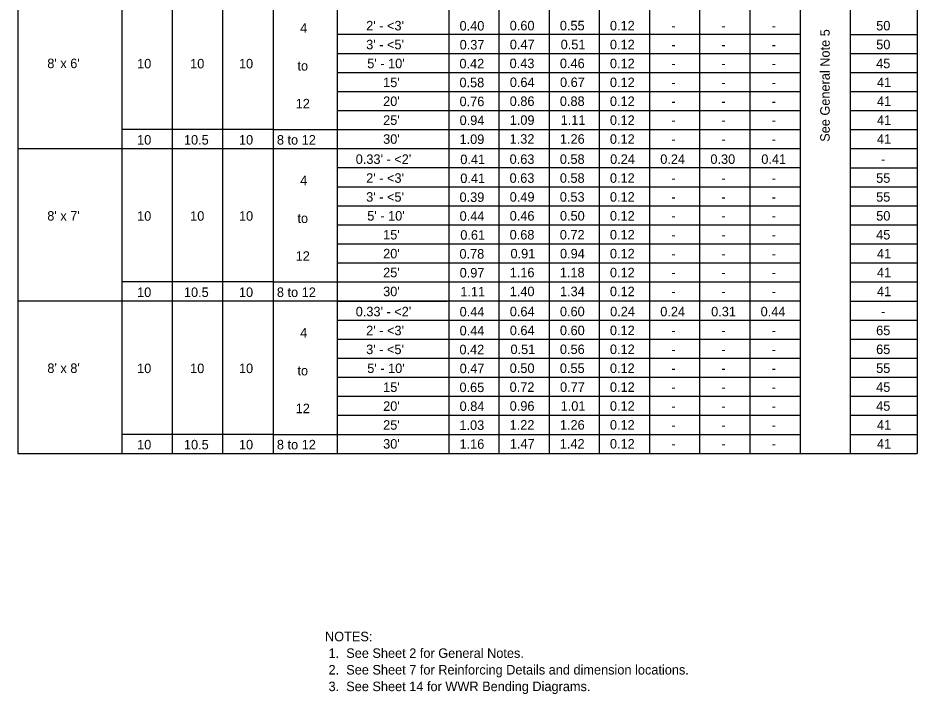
# Model space of a CAD drawing. Extents: x 10342.77 to 10344.98, y 76371.53 to 76372.62.
# Drawn here: x 10343.418 to 10344.012, y 76371.801 to 76372.249 of the extents above; entities that cross this region are included whole.
import ezdxf

# ---------------------------------------------------------------- set-up
doc = ezdxf.new("R2010")
doc.units = 0
doc.layers.add('AdhocPoint_dp', color=7, linetype='Continuous')
doc.layers.add('PlotBorder_dp', color=7, linetype='Continuous')

msp = doc.modelspace()

# ---------------------------------------------------------------- linework, layer by layer
at = {"layer": 'PlotBorder_dp'}
for p, q in [((10343.41763, 76372.53475), (10343.41763, 76371.96053)), ((10344.01237, 76372.53475), (10344.01237, 76371.96053)), ((10343.48627, 76372.51488), (10343.48627, 76371.96053)), ((10343.62871, 76372.51488), (10343.62871, 76371.96053)), ((10343.70259, 76372.51488), (10343.70259, 76371.96053)), ((10343.96818, 76372.51488), (10343.96818, 76371.96053)), ((10343.51963, 76372.50228), (10343.51963, 76371.96053)), ((10343.55299, 76372.50228), (10343.55299, 76371.96053)), ((10343.58635, 76372.50228), (10343.58635, 76371.96053)), ((10343.73579, 76372.47713), (10343.73579, 76371.96053)), ((10343.76899, 76372.47713), (10343.76899, 76371.96053)), ((10343.80219, 76372.47713), (10343.80219, 76371.96053)), ((10343.83539, 76372.47713), (10343.83539, 76371.96053)), ((10343.86858, 76372.47713), (10343.86858, 76371.96053)), ((10343.86858, 76372.47713), (10343.86858, 76371.96053)), ((10343.90178, 76372.47713), (10343.90178, 76371.96053)), ((10343.93498, 76372.47713), (10343.93498, 76371.96053)), ((10343.62871, 76372.23773), (10343.93498, 76372.23773)), ((10343.96818, 76372.23771), (10344.01237, 76372.23771)), ((10343.62871, 76372.22513), (10343.93498, 76372.22513)), ((10343.96818, 76372.22511), (10344.01237, 76372.22511)), ((10343.62871, 76372.21253), (10343.93498, 76372.21253)), ((10343.96818, 76372.21251), (10344.01237, 76372.21251)), ((10343.62871, 76372.19993), (10343.93498, 76372.19993)), ((10343.96818, 76372.19991), (10344.01237, 76372.19991)), ((10343.62871, 76372.18733), (10343.93498, 76372.18733)), ((10343.96818, 76372.18731), (10344.01237, 76372.18731)), ((10343.58635, 76372.17473), (10343.48627, 76372.17473)), ((10343.58635, 76372.17473), (10343.93498, 76372.17473)), ((10343.96818, 76372.17471), (10344.01237, 76372.17471)), ((10343.41763, 76372.16213), (10343.93498, 76372.16213)), ((10343.62931, 76372.16211), (10343.70148, 76372.16211)), ((10343.96818, 76372.16211), (10344.01237, 76372.16211)), ((10343.62871, 76372.14953), (10343.93498, 76372.14953)), ((10343.96818, 76372.14951), (10344.01237, 76372.14951)), ((10343.62871, 76372.13693), (10343.93498, 76372.13693)), ((10343.96818, 76372.13691), (10344.01237, 76372.13691)), ((10343.62871, 76372.12433), (10343.93498, 76372.12433)), ((10343.96818, 76372.12431), (10344.01237, 76372.12431)), ((10343.62871, 76372.11173), (10343.93498, 76372.11173)), ((10343.96818, 76372.11171), (10344.01237, 76372.11171)), ((10343.62871, 76372.09913), (10343.93498, 76372.09913)), ((10343.96818, 76372.09911), (10344.01237, 76372.09911)), ((10343.62871, 76372.08653), (10343.93498, 76372.08653)), ((10343.96818, 76372.08651), (10344.01237, 76372.08651)), ((10343.58635, 76372.07393), (10343.48627, 76372.07393)), ((10343.58635, 76372.07393), (10343.93498, 76372.07393)), ((10343.96818, 76372.07391), (10344.01237, 76372.07391)), ((10343.41763, 76372.06133), (10343.93498, 76372.06133)), ((10343.62931, 76372.06131), (10343.70148, 76372.06131)), ((10343.96818, 76372.06131), (10344.01237, 76372.06131)), ((10343.62871, 76372.04873), (10343.93498, 76372.04873)), ((10343.96818, 76372.04871), (10344.01237, 76372.04871)), ((10343.62871, 76372.03613), (10343.93498, 76372.03613)), ((10343.96818, 76372.03611), (10344.01237, 76372.03611)), ((10343.62871, 76372.02353), (10343.93498, 76372.02353)), ((10343.96818, 76372.02351), (10344.01237, 76372.02351)), ((10343.62871, 76372.01093), (10343.93498, 76372.01093)), ((10343.96818, 76372.01091), (10344.01237, 76372.01091)), ((10343.62871, 76371.99833), (10343.93498, 76371.99833)), ((10343.96818, 76371.99831), (10344.01237, 76371.99831)), ((10343.62871, 76371.98573), (10343.93498, 76371.98573)), ((10343.96818, 76371.98571), (10344.01237, 76371.98571)), ((10343.58635, 76371.97313), (10343.48627, 76371.97313)), ((10343.58635, 76371.97311), (10343.70148, 76371.97311)), ((10343.62871, 76371.97313), (10343.93498, 76371.97313)), ((10343.96818, 76371.97311), (10344.01237, 76371.97311)), ((10343.41763, 76371.96053), (10344.01237, 76371.96053))]:
    msp.add_line(p, q, dxfattribs=at)

# ---------------------------------------------------------------- texts
at = {"layer": 'AdhocPoint_dp'}
msp.add_text('See General Note 5', height=0.0063, rotation=90, dxfattribs=at).set_placement((10343.95463, 76372.16663))
for s, p in [('10', (10343.49644, 76372.21519)), ('10', (10343.53153, 76372.21519)), ('10', (10343.56382, 76372.21519)), ('10', (10343.49643, 76372.16478)), ('10.5', (10343.52742, 76372.16478)), ('10', (10343.56381, 76372.16478)), ('8 to 12', (10343.58891, 76372.16478)), ('10', (10343.49644, 76372.11441)), ('10', (10343.53153, 76372.11441)), ('10', (10343.56382, 76372.11441)), ('10', (10343.49643, 76372.06398)), ('10.5', (10343.52742, 76372.06398)), ('10', (10343.56381, 76372.06398)), ('8 to 12', (10343.58891, 76372.06398)), ('10', (10343.49644, 76372.01363)), ('10', (10343.53153, 76372.01363)), ('10', (10343.56382, 76372.01363)), ('10', (10343.49643, 76371.96318)), ('10.5', (10343.52742, 76371.96318)), ('10', (10343.56381, 76371.96318)), ('8 to 12', (10343.58891, 76371.96318))]:
    msp.add_text(s, height=0.0063, dxfattribs=at).set_placement(p)
at = {"layer": 'PlotBorder_dp'}
for s, p in [('4', (10343.60429, 76372.23873)), ("2' - <3'", (10343.64797, 76372.2403)), ('0.40', (10343.70975, 76372.24019)), ('0.60', (10343.74294, 76372.24035)), ('0.55', (10343.77609, 76372.24035)), ('0.12', (10343.80922, 76372.2403)), ('50', (10343.98538, 76372.2403)), ('-', (10343.84981, 76372.2403)), ('-', (10343.88302, 76372.2403)), ('-', (10343.9162, 76372.2403)), ("3' - <5'", (10343.64797, 76372.2278)), ('0.37', (10343.70981, 76372.22769)), ('0.47', (10343.74301, 76372.22785)), ('0.51', (10343.77663, 76372.22785)), ('0.12', (10343.80922, 76372.2278)), ('50', (10343.98538, 76372.2278)), ('-', (10343.84981, 76372.2278)), ('-', (10343.88302, 76372.2278)), ('-', (10343.9162, 76372.2278)), ("8' x 6'", (10343.43702, 76372.21535)), ("5' - 10'", (10343.64868, 76372.2153)), ('0.42', (10343.70967, 76372.21519)), ('0.43', (10343.74286, 76372.21535)), ('0.46', (10343.77613, 76372.21535)), ('0.12', (10343.80922, 76372.2153)), ('45', (10343.98533, 76372.2153)), ('to', (10343.60251, 76372.21373)), ('-', (10343.84981, 76372.2153)), ('-', (10343.88302, 76372.2153)), ('-', (10343.9162, 76372.2153)), ("15'", (10343.6592, 76372.2028)), ('0.58', (10343.70969, 76372.20269)), ('0.64', (10343.74299, 76372.20285)), ('0.67', (10343.77621, 76372.20285)), ('0.12', (10343.80922, 76372.2028)), ('41', (10343.98587, 76372.2028)), ('-', (10343.84981, 76372.2028)), ('-', (10343.88302, 76372.2028)), ('-', (10343.9162, 76372.2028)), ('12', (10343.60134, 76372.18873)), ("20'", (10343.6592, 76372.1903)), ('0.76', (10343.70973, 76372.19019)), ('0.86', (10343.74293, 76372.19035)), ('0.88', (10343.77609, 76372.19035)), ('0.12', (10343.80922, 76372.1903)), ('-', (10343.84981, 76372.1903)), ('-', (10343.88302, 76372.1903)), ('-', (10343.9162, 76372.1903)), ('41', (10343.98587, 76372.1903)), ("25'", (10343.6592, 76372.1778)), ('0.94', (10343.70979, 76372.17769)), ('1.09', (10343.74293, 76372.17785)), ('1.11', (10343.77663, 76372.17785)), ('0.12', (10343.80922, 76372.1778)), ('-', (10343.84981, 76372.1778)), ('-', (10343.88302, 76372.1778)), ('-', (10343.9162, 76372.1778)), ('41', (10343.98587, 76372.1778)), ("30'", (10343.6592, 76372.1653)), ('1.09', (10343.70973, 76372.16519)), ('1.32', (10343.74287, 76372.16535)), ('1.26', (10343.77613, 76372.16535)), ('0.12', (10343.80922, 76372.1653)), ('-', (10343.84981, 76372.1653)), ('-', (10343.88302, 76372.1653)), ('-', (10343.9162, 76372.1653)), ('41', (10343.98587, 76372.1653)), ("0.33' - <2'", (10343.64107, 76372.15201)), ('0.41', (10343.71024, 76372.15186)), ('0.63', (10343.74286, 76372.15201)), ('0.58', (10343.77609, 76372.15201)), ('0.24', (10343.80935, 76372.15201)), ('0.24', (10343.84253, 76372.15201)), ('0.30', (10343.87569, 76372.15201)), ('0.41', (10343.90936, 76372.15201)), ('-', (10343.98864, 76372.15201)), ('4', (10343.60429, 76372.13793)), ("2' - <3'", (10343.64797, 76372.13951)), ('0.41', (10343.71024, 76372.13936)), ('0.63', (10343.74286, 76372.13951)), ('0.58', (10343.77609, 76372.13951)), ('0.12', (10343.80922, 76372.13951)), ('55', (10343.98533, 76372.13951)), ('-', (10343.84981, 76372.13951)), ('-', (10343.88302, 76372.13951)), ('- ', (10343.9162, 76372.13951)), ("3' - <5'", (10343.64797, 76372.12701)), ('0.39', (10343.70973, 76372.12686)), ('0.49', (10343.74293, 76372.12701)), ('0.53', (10343.77606, 76372.12701)), ('0.12', (10343.80922, 76372.12701)), ('55', (10343.98533, 76372.12701)), ('-', (10343.84981, 76372.12701)), ('-', (10343.88302, 76372.12701)), ('-', (10343.9162, 76372.12701)), ("8' x 7'", (10343.43702, 76372.11451)), ("5' - 10'", (10343.64868, 76372.11451)), ('0.44', (10343.70979, 76372.11436)), ('0.46', (10343.74293, 76372.11451)), ('0.50', (10343.77615, 76372.11451)), ('0.12', (10343.80922, 76372.11451)), ('50', (10343.98538, 76372.11451)), ('to', (10343.60251, 76372.11293)), ('-', (10343.84981, 76372.11451)), ('-', (10343.88302, 76372.11451)), ('-', (10343.9162, 76372.11451)), ("15'", (10343.6592, 76372.10201)), ('0.61', (10343.71024, 76372.10186)), ('0.68', (10343.74288, 76372.10201)), ('0.72', (10343.77607, 76372.10201)), ('0.12', (10343.80922, 76372.10201)), ('45', (10343.98533, 76372.10201)), ('-', (10343.84981, 76372.10201)), ('-', (10343.88302, 76372.10201)), ('-', (10343.9162, 76372.10201)), ('12', (10343.60134, 76372.08793)), ("20'", (10343.6592, 76372.08951)), ('0.78', (10343.70969, 76372.08936)), ('0.91', (10343.74343, 76372.08951)), ('0.94', (10343.77619, 76372.08951)), ('0.12', (10343.80922, 76372.08951)), ('-', (10343.84981, 76372.08951)), ('-', (10343.88302, 76372.08951)), ('-', (10343.9162, 76372.08951)), ('41', (10343.98587, 76372.08951)), ("25'", (10343.6592, 76372.07701)), ('0.97', (10343.70981, 76372.07686)), ('1.16', (10343.74293, 76372.07701)), ('1.18', (10343.77609, 76372.07701)), ('0.12', (10343.80922, 76372.07701)), ('-', (10343.84981, 76372.07701)), ('-', (10343.88302, 76372.07701)), ('-', (10343.9162, 76372.07701)), ('41', (10343.98587, 76372.07701)), ("30'", (10343.6592, 76372.06451)), ('1.11', (10343.71024, 76372.06436)), ('1.40', (10343.74294, 76372.06451)), ('1.34', (10343.77619, 76372.06451)), ('0.12', (10343.80922, 76372.06451)), ('-', (10343.84981, 76372.06451)), ('-', (10343.88302, 76372.06451)), ('-', (10343.9162, 76372.06451)), ('41', (10343.98587, 76372.06451)), ("0.33' - <2'", (10343.64107, 76372.05118)), ('0.44', (10343.70979, 76372.05108)), ('0.64', (10343.74299, 76372.05123)), ('0.60', (10343.77615, 76372.05123)), ('0.24', (10343.80935, 76372.05123)), ('0.24', (10343.84253, 76372.05118)), ('0.31', (10343.87618, 76372.05118)), ('0.44', (10343.90892, 76372.05118)), ('-', (10343.98864, 76372.05123)), ('4', (10343.60429, 76372.03713)), ("2' - <3'", (10343.64797, 76372.03868)), ('0.44', (10343.70979, 76372.03858)), ('0.64', (10343.74299, 76372.03873)), ('0.60', (10343.77615, 76372.03873)), ('0.12', (10343.80922, 76372.03873)), ('65', (10343.98533, 76372.03873)), ('-', (10343.84981, 76372.03868)), ('-', (10343.88302, 76372.03868)), ('- ', (10343.9162, 76372.03868)), ("3' - <5'", (10343.64797, 76372.02618)), ('0.42', (10343.70967, 76372.02608)), ('0.51', (10343.74343, 76372.02623)), ('0.56', (10343.77613, 76372.02623)), ('0.12', (10343.80922, 76372.02623)), ('65', (10343.98533, 76372.02623)), ('-', (10343.84981, 76372.02618)), ('-', (10343.88302, 76372.02618)), ('-', (10343.9162, 76372.02618)), ("8' x 8'", (10343.43707, 76372.01373)), ("5' - 10'", (10343.64868, 76372.01368)), ('0.47', (10343.70981, 76372.01358)), ('0.50', (10343.74294, 76372.01373)), ('0.55', (10343.77609, 76372.01373)), ('0.12', (10343.80922, 76372.01373)), ('55', (10343.98533, 76372.01373)), ('to', (10343.60251, 76372.01213)), ('-', (10343.84981, 76372.01368)), ('-', (10343.88302, 76372.01368)), ('-', (10343.9162, 76372.01368)), ("15'", (10343.6592, 76372.00118)), ('0.65', (10343.70969, 76372.00108)), ('0.72', (10343.74287, 76372.00123)), ('0.77', (10343.77621, 76372.00123)), ('0.12', (10343.80922, 76372.00123)), ('45', (10343.98533, 76372.00123)), ('-', (10343.84981, 76372.00118)), ('-', (10343.88302, 76372.00118)), ('-', (10343.9162, 76372.00118)), ("20'", (10343.6592, 76371.98868)), ('0.84', (10343.70979, 76371.98858)), ('0.96', (10343.74293, 76371.98873)), ('1.01', (10343.77663, 76371.98873)), ('0.12', (10343.80922, 76371.98873)), ('45', (10343.98533, 76371.98873)), ('12', (10343.60134, 76371.98713)), ('-', (10343.84981, 76371.98868)), ('-', (10343.88302, 76371.98868)), ('-', (10343.9162, 76371.98868)), ("25'", (10343.6592, 76371.97618)), ('1.03', (10343.70966, 76371.97608)), ('1.22', (10343.74287, 76371.97623)), ('1.26', (10343.77613, 76371.97623)), ('0.12', (10343.80922, 76371.97623)), ('-', (10343.84981, 76371.97618)), ('-', (10343.88302, 76371.97618)), ('-', (10343.9162, 76371.97618)), ('41', (10343.98587, 76371.97623)), ("30'", (10343.6592, 76371.96368)), ('1.16', (10343.70973, 76371.96358)), ('1.47', (10343.74301, 76371.96373)), ('1.42', (10343.77607, 76371.96373)), ('0.12', (10343.80922, 76371.96373)), ('-', (10343.84981, 76371.96368)), ('-', (10343.88302, 76371.96368)), ('-', (10343.9162, 76371.96368)), ('41', (10343.98587, 76371.96373)), ('NOTES:', (10343.62073, 76371.83627)), (' 1.  See Sheet 2 for General Notes.', (10343.62073, 76371.82527)), (' 2.  See Sheet 7 for Reinforcing Details and dimension locations.', (10343.62073, 76371.81427)), (' 3.  See Sheet 14 for WWR Bending Diagrams.', (10343.62073, 76371.80327))]:
    msp.add_text(s, height=0.0063, dxfattribs=at).set_placement(p)

doc.saveas('drawing.dxf')
